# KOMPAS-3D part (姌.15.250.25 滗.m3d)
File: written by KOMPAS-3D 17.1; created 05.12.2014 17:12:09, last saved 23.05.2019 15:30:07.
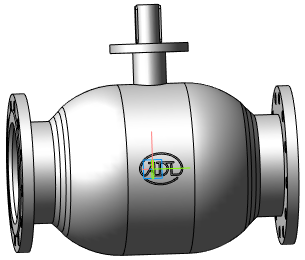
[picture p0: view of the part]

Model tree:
1. Операция без истории:6  (labels: Сталь 20  ГОСТ 1050-88)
